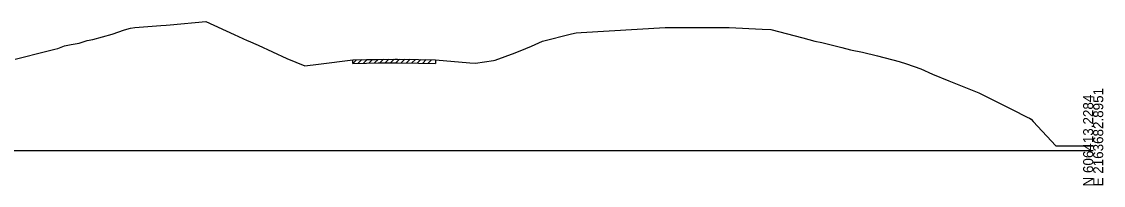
# Model space of a CAD drawing. Extents: x -26 to 6803, y -10 to 19606.
# Drawn here: x 6500.9 to 6802.8, y 4490.3 to 4536 of the extents above; entities that cross this region are included whole.
import ezdxf

# ---------------------------------------------------------------- set-up
doc = ezdxf.new("R2010")
doc.units = 0
for name, color, linetype in [('RD_GPK_XS_Cell', 7, 'Continuous'), ('RD_XS_ExGround', 7, 'Continuous'), ('RD_XS_ExPaveRet', 7, 'Continuous')]:
    doc.layers.add(name, color=color, linetype=linetype)

msp = doc.modelspace()

# ---------------------------------------------------------------- linework, layer by layer
at = {"layer": 'RD_GPK_XS_Cell'}
msp.add_line((6400, 4500), (6800, 4500), dxfattribs=at)
at = {"layer": 'RD_XS_ExGround'}
msp.add_lwpolyline([(6499.06, 4525.49), (6507.87, 4527.76), (6510.17, 4528.32), (6510.95, 4528.47), (6512.83, 4529.2), (6514.74, 4529.57), (6516.9, 4529.95), (6519.19, 4530.71), (6520.72, 4531.05), (6526.16, 4532.5), (6529.59, 4533.69), (6531.23, 4534.21), (6532.47, 4534.35), (6539.73, 4534.93), (6541.25, 4535.05), (6542.34, 4535.14), (6552.33, 4535.99), (6560.22, 4532.37), (6563.82, 4530.77), (6564.14, 4530.59), (6566.88, 4529.39), (6574.93, 4525.75), (6579.89, 4523.68), (6583.79, 4524.13), (6593.34, 4525.31), (6597.14, 4525.42), (6600.39, 4525.46), (6605.03, 4525.54), (6605.81, 4525.53), (6611.63, 4525.44), (6616.41, 4525.35), (6625.95, 4524.48), (6627.61, 4524.37), (6632.6, 4525.15), (6633.03, 4525.21), (6638.66, 4527.3), (6641.64, 4528.46), (6643.19, 4529.1), (6646.3, 4530.54), (6654.38, 4532.54), (6655.64, 4532.84), (6657.06, 4532.93), (6680.52, 4534.35), (6685.77, 4534.33), (6693.86, 4534.38), (6698.36, 4534.32), (6707.56, 4533.87), (6709.99, 4533.75), (6718.95, 4531.46), (6722.29, 4530.54), (6724.27, 4530.15), (6726.9, 4529.55), (6729.83, 4528.78), (6732.29, 4528.16), (6735.58, 4527.49), (6739.82, 4526.42), (6745.81, 4524.89), (6747.91, 4524.22), (6751.93, 4522.79), (6755.14, 4521.35), (6759.74, 4519.48), (6768.12, 4516.08), (6777.39, 4511.51), (6781.61, 4509.31), (6782.18, 4509.02), (6782.67, 4508.82), (6783.2, 4508.14), (6789.54, 4501.34), (6791.1, 4501.34), (6793.1, 4501.34), (6800, 4501.34)], dxfattribs=at)
at = {"layer": 'RD_XS_ExPaveRet'}
for p, q in [((6593.34, 4524.31), (6594.37, 4525.34)), ((6593.34, 4524.31), (6593.34, 4525.31)), ((6593.34, 4524.31), (6597.14, 4524.42)), ((6593.34, 4524.31), (6593.34, 4524.31)), ((6594.84, 4524.36), (6595.87, 4525.38)), ((6596.34, 4524.4), (6597.37, 4525.42)), ((6597.14, 4524.42), (6600.39, 4524.46)), ((6597.84, 4524.43), (6598.86, 4525.44)), ((6599.34, 4524.45), (6600.36, 4525.46)), ((6600.39, 4524.46), (6605.03, 4524.54)), ((6600.84, 4524.47), (6601.86, 4525.49)), ((6602.34, 4524.49), (6603.36, 4525.51)), ((6603.84, 4524.52), (6604.86, 4525.54)), ((6605.03, 4524.54), (6605.81, 4524.53)), ((6605.34, 4524.54), (6606.33, 4525.53)), ((6605.81, 4524.53), (6611.63, 4524.44)), ((6606.84, 4524.52), (6607.83, 4525.5)), ((6608.34, 4524.49), (6609.33, 4525.48)), ((6609.84, 4524.47), (6610.83, 4525.46)), ((6611.34, 4524.45), (6612.32, 4525.43)), ((6611.63, 4524.44), (6616.41, 4524.35)), ((6612.84, 4524.42), (6613.82, 4525.4)), ((6614.34, 4524.39), (6615.32, 4525.37)), ((6616.41, 4525.35), (6616.41, 4524.35))]:
    msp.add_line(p, q, dxfattribs=at)

# ---------------------------------------------------------------- texts
at = {"layer": 'RD_GPK_XS_Cell'}
for s, p in [('N 606413.2284', (6800, 4490)), ('E 2163682.8951', (6802.8, 4490))]:
    msp.add_text(s, height=2.8, rotation=90, dxfattribs=at).set_placement(p)

doc.saveas('drawing.dxf')
